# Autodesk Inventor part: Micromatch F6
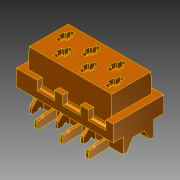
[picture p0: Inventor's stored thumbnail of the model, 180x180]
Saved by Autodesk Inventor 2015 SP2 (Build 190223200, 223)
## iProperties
Created: 2013-08
Part Number: Micromatch F6
Material: Nylon 6/6
Document SubType Name: Modeling
Designer: rYan
Density: 1.13 g/cm^3
Appearance: Nylon 6
Übersetzungsnorm: IGES 5.2
Dateiname: c-7-188275-6-u-3d.igs
Vorprozessor: Pro/ENGINEER by Parametric Technology Corporation
Postprozessor: Build: 138, Release: 2013 RTM - Date: Thu 03/01/2012
Gesendete Einheiten: Millimeter
Unbestimmtheit: 0.00128982
Author: rYan
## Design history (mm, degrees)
node "c-7-188275-6-u-3d1"
feature "Zusammengesetzt1"
node "Fläche1"
